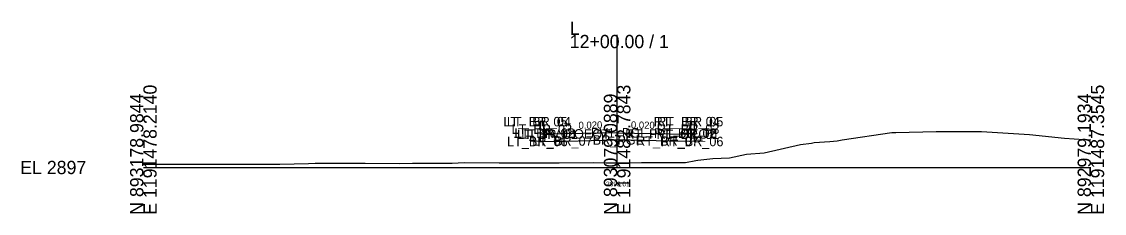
# Model space of a CAD drawing. Extents: x -26 to 203, y -10 to 7027.
# Drawn here: x -25.7 to 202.8, y 3990.3 to 4030.8 of the extents above; entities that cross this region are included whole.
import ezdxf

# ---------------------------------------------------------------- set-up
doc = ezdxf.new("R2010")
doc.units = 0
for name, color, linetype in [('Default', 7, 'Continuous'), ('Exist Cross Section Cell', 7, 'Continuous'), ('Prop CMT Pvmt Course 2 Wedge', 7, 'Continuous'), ('Prop CMT Pvmt Course 3 Wedge', 7, 'Continuous'), ('Prop CMT Pvmt Surface Shoulder', 7, 'Continuous'), ('Prop CMT Pvmt Wedge Surface 1', 7, 'Continuous'), ('Scratch_Level_6', 7, 'Continuous')]:
    doc.layers.add(name, color=color, linetype=linetype)

msp = doc.modelspace()

# ---------------------------------------------------------------- linework, layer by layer
at = {"layer": 'Exist Cross Section Cell'}
for p, q in [((100, 4000), (100, 4028)), ((0, 4000), (100, 4000)), ((100, 4000), (200, 4000))]:
    msp.add_line(p, q, dxfattribs=at)
at = {"layer": 'Prop CMT Pvmt Course 3 Wedge'}
for p, q in [((147.51, 4005.82), (157.97, 4007.36)), ((157.97, 4007.36), (158.46, 4007.38)), ((158.46, 4007.38), (158.81, 4007.39)), ((158.81, 4007.39), (167.33, 4007.57)), ((167.33, 4007.57), (170.02, 4007.6)), ((170.02, 4007.6), (176.9, 4007.58)), ((176.9, 4007.58), (187.02, 4006.95)), ((187.02, 4006.95), (194.41, 4006.21)), ((194.41, 4006.21), (198.49, 4005.9)), ((131.06, 4003.08), (138.67, 4004.88)), ((138.67, 4004.88), (141.04, 4005.15)), ((141.04, 4005.15), (141.58, 4005.28)), ((141.58, 4005.28), (144.88, 4005.52)), ((144.88, 4005.52), (146.47, 4005.66)), ((146.47, 4005.66), (147.51, 4005.82)), ((198.49, 4005.9), (200, 4005.84)), ((117.03, 4001.52), (120.2, 4001.86)), ((120.2, 4001.86), (123.7, 4002.07)), ((123.7, 4002.07), (127.33, 4002.81)), ((127.33, 4002.81), (131.06, 4003.08)), ((0, 4000.66), (2.06, 4000.67)), ((2.06, 4000.67), (5.86, 4000.67)), ((5.86, 4000.67), (10.52, 4000.68)), ((10.52, 4000.68), (15.98, 4000.69)), ((15.98, 4000.69), (18.76, 4000.69)), ((18.76, 4000.69), (26.12, 4000.7)), ((26.12, 4000.7), (26.74, 4000.7)), ((26.74, 4000.7), (28.79, 4000.71)), ((28.79, 4000.71), (34.83, 4000.87)), ((34.83, 4000.87), (36.28, 4000.9)), ((36.28, 4000.9), (36.77, 4000.91)), ((36.77, 4000.91), (44.82, 4000.88)), ((44.82, 4000.88), (46.78, 4000.89)), ((46.78, 4000.89), (54.16, 4000.86)), ((54.16, 4000.86), (56.81, 4000.9)), ((56.81, 4000.9), (61.94, 4000.88)), ((61.94, 4000.88), (65.15, 4000.94)), ((65.15, 4000.94), (67.72, 4001.04)), ((67.72, 4001.04), (75.08, 4000.96)), ((75.08, 4000.96), (77.69, 4001.01)), ((77.69, 4001.01), (84.99, 4000.95)), ((84.99, 4000.95), (86.06, 4000.95)), ((86.06, 4000.95), (87.76, 4000.96)), ((87.76, 4000.96), (94.92, 4001.02)), ((94.92, 4001.02), (97.68, 4000.99)), ((97.68, 4000.99), (100, 4001.01)), ((100, 4001.01), (105.13, 4001.05)), ((105.13, 4001.05), (107.6, 4001.03)), ((107.6, 4001.03), (112.95, 4001.07)), ((112.95, 4001.07), (114.4, 4001.06)), ((114.4, 4001.06), (116.58, 4001.48)), ((116.58, 4001.48), (117.03, 4001.52))]:
    msp.add_line(p, q, dxfattribs=at)
at = {"layer": 'Prop CMT Pvmt Wedge Surface 1'}
for points in [[(100, 4007.31), (89, 4007.09), (85.25, 4007.01), (85.24, 4007.26), (84.66, 4008.1), (84.49, 4009.68), (83.75, 4009.68), (83.75, 4005.48)], [(100, 4007.31), (111, 4007.09), (114.75, 4007.01), (114.76, 4007.26), (115.34, 4008.1), (115.51, 4009.68), (116.25, 4009.68), (116.25, 4005.48)], [(100, 4005.81), (100, 4007.31)], [(100, 4005.81), (100, 4007.31)], [(83.75, 4005.48), (89, 4005.59), (100, 4005.81)], [(116.25, 4005.48), (111, 4005.59), (100, 4005.81)]]:
    msp.add_lwpolyline(points, dxfattribs=at)

# ---------------------------------------------------------------- texts
at = {"layer": 'Default'}
msp.add_text('-', height=0.0001, dxfattribs=at).set_placement((0, 4000))
at = {"layer": 'Exist Cross Section Cell'}
for s, p in [('L', (90, 4028)), ('12+00.00 / 1', (90, 4025.2)), ('EL 2897', (-26, 3998.6))]:
    msp.add_text(s, height=2.8, dxfattribs=at).set_placement(p)
for s, p in [('N 893178.9844', (0, 3990)), ('E 1191478.2140', (2.8, 3990)), ('N 893079.0889', (100, 3990)), ('E 1191482.7843', (102.8, 3990)), ('N 892979.1934', (200, 3990)), ('E 1191487.3545', (202.8, 3990))]:
    msp.add_text(s, height=2.8, rotation=90, dxfattribs=at).set_placement(p)
at = {"layer": 'Prop CMT Pvmt Course 2 Wedge'}
for s, p in [('LT_ BR_05', (75.99, 4008.68)), ('LT_ BR_04', (76.73, 4008.68)), ('LT_BR_03', (77.71, 4007.1)), ('RT_ BR_04', (107.7, 4008.68)), ('RT_BR_03', (108.35, 4007.1)), ('RT_ BR_05', (108.44, 4008.68)), ('LT_BR_06', (76.76, 4004.48)), ('LT_BR_02', (78.3, 4006.26)), ('LT_BR_01', (78.87, 4006.01)), ('LT_PV1_OEOT', (79.74, 4006.09)), ('LT_BR_07', (82.06, 4004.59)), ('PV1_PGL', (94.47, 4006.31)), ('BR_PGL', (94.83, 4004.81)), ('RT_PV1_OEOT', (101.69, 4006.09)), ('RT_BR_07', (104.01, 4004.59)), ('RT_BR_02', (107.77, 4006.26)), ('RT_BR_01', (108.32, 4006.01)), ('RT_BR_06', (109.21, 4004.48))]:
    msp.add_text(s, height=2, dxfattribs=at).set_placement(p)
at = {"layer": 'Prop CMT Pvmt Surface Shoulder'}
for rotation, p in [(1.1458, (91.86, 4008.15)), (358.8542, (102.9, 4008.25))]:
    msp.add_text('0.020', height=1.5, rotation=rotation, dxfattribs=at).set_placement(p)
at = {"layer": 'Scratch_Level_6'}
msp.add_text('2898.01', height=1, dxfattribs=at).set_placement((97.66, 3996.01))

doc.saveas('drawing.dxf')
